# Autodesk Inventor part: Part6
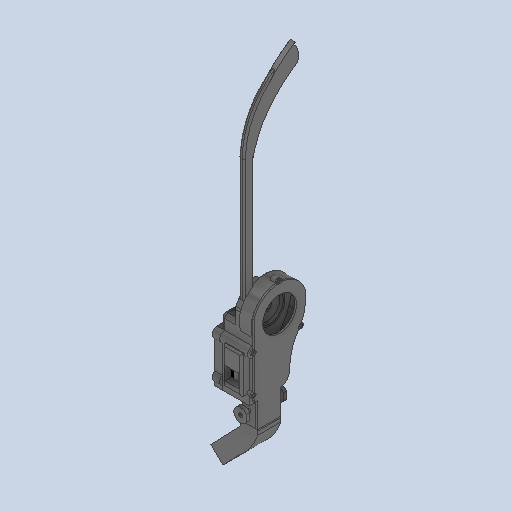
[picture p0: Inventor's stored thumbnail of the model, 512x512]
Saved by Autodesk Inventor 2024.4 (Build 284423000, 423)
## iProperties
Created: 2025-05
Part Number: Part6
Material: Generic
Document SubType Name: Modeling
Designer: AdminForWorker
Density: 1 g/cm^3
Appearance: Default
Author: AdminForWorker
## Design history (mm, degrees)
feature "fan_top" [Body]
feature "MAIN" [Body]
feature "Body40"
feature "Body43"
feature "MAIN (1)" [Body]
feature "ESP_top" [Body]
body "Solid1"
body "Solid2"
body "Solid3"
body "Solid4"
body "Solid5"
body "Solid6"
